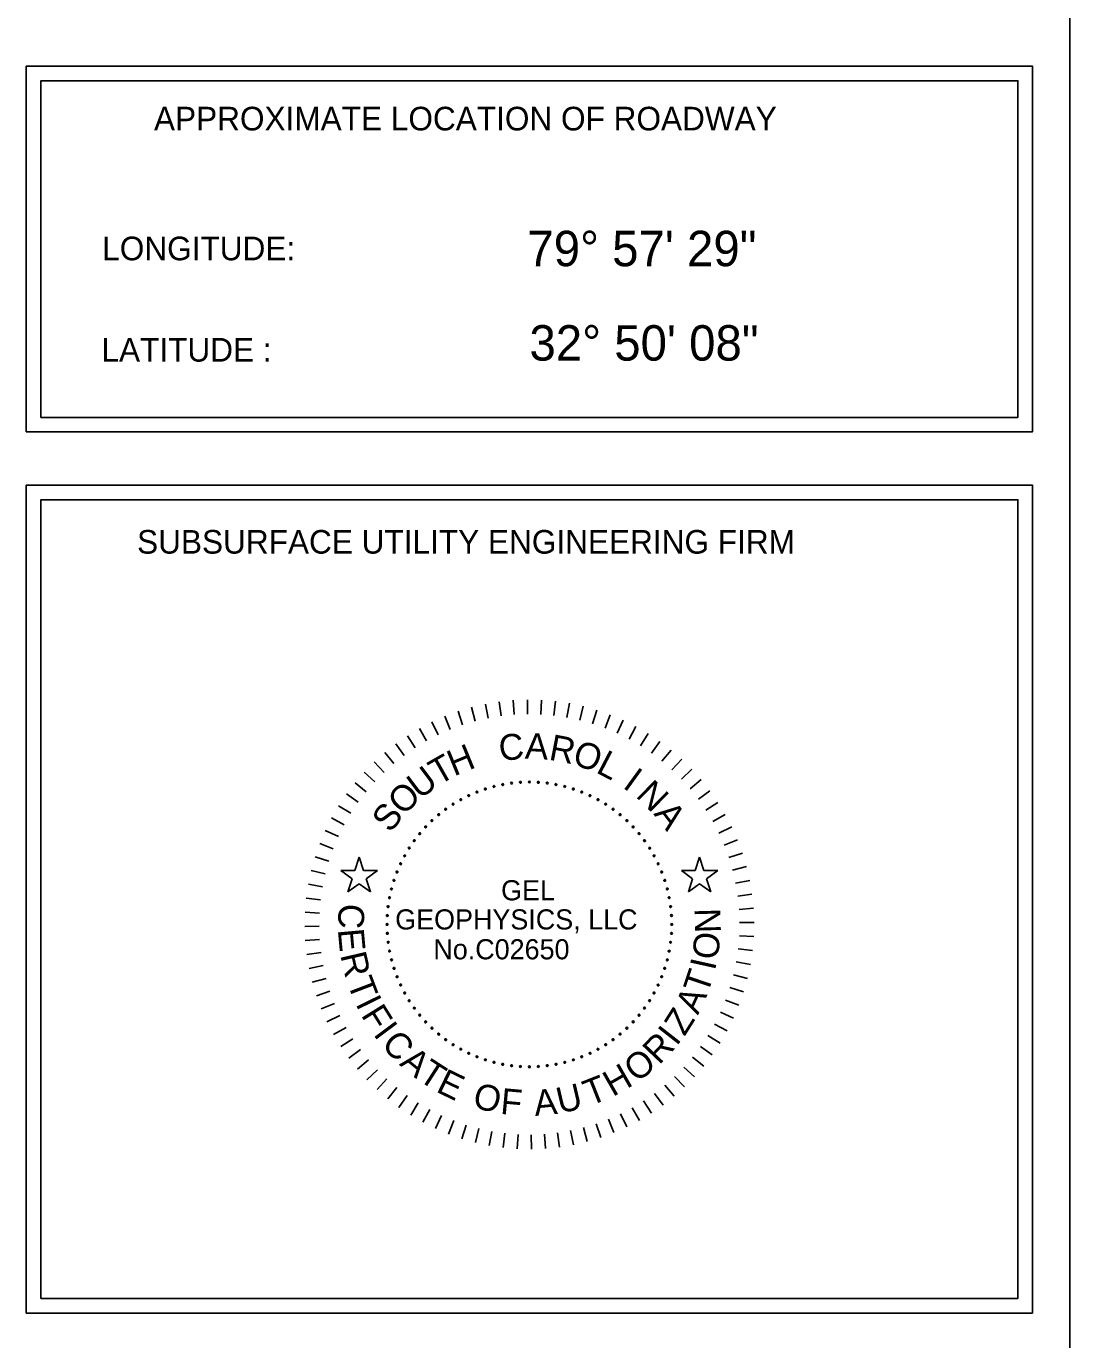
# Model space of a CAD drawing. Extents: x 190073 to 191750, y 195724 to 196797.
# Drawn here: x 191526.6 to 191747.6, y 196008.5 to 196286.5 of the extents above; entities that cross this region are included whole.
import ezdxf

# ---------------------------------------------------------------- set-up
doc = ezdxf.new("R2010")
doc.units = 0
for name, color, linetype in [('RD_EX_SU_H2O', 7, 'Continuous'), ('RD_SHT_Bndy', 7, 'Continuous'), ('RD_SHT_TX', 7, 'Continuous')]:
    doc.layers.add(name, color=color, linetype=linetype)

# ---------------------------------------------------------------- blocks, each defined once
blk = doc.blocks.new('GEGSC')
for p, q in [((-0.6324, 0.1948), (-0.6485, 0.1451)), ((-0.6162, 0.1451), (-0.6324, 0.1948)), ((0.6313, 0.1451), (0.6474, 0.1948)), ((0.6474, 0.1948), (0.6635, 0.1451)), ((-0.6485, 0.1451), (-0.7007, 0.1451)), ((-0.7007, 0.1451), (-0.6585, 0.1144)), ((-0.6585, 0.1144), (-0.6746, 0.0648)), ((-0.564, 0.1451), (-0.6162, 0.1451)), ((-0.6063, 0.1144), (-0.564, 0.1451)), ((-0.5901, 0.0648), (-0.6063, 0.1144)), ((0.5791, 0.1451), (0.6313, 0.1451)), ((0.6213, 0.1144), (0.5791, 0.1451)), ((0.6052, 0.0648), (0.6213, 0.1144)), ((0.6635, 0.1451), (0.7158, 0.1451)), ((0.7158, 0.1451), (0.6735, 0.1144)), ((0.6735, 0.1144), (0.6897, 0.0648)), ((-0.6746, 0.0648), (-0.6324, 0.0955)), ((-0.6324, 0.0955), (-0.5901, 0.0648)), ((0.6474, 0.0955), (0.6052, 0.0648)), ((0.6897, 0.0648), (0.6474, 0.0955))]:
    blk.add_line(p, q)
for points in [[(-0.2605, 0.7434), (-0.2434, 0.6922)], [(-0.2097, 0.7587), (-0.1958, 0.7064)], [(-0.158, 0.7707), (-0.1474, 0.7177)], [(-0.1057, 0.7795), (-0.0985, 0.7259)], [(-0.0529, 0.7849), (-0.0491, 0.731)], [(0.0001, 0.7871), (0.0006, 0.733)], [(0.0531, 0.7859), (0.0502, 0.7319)], [(0.106, 0.7813), (0.0997, 0.7276)], [(0.1585, 0.7735), (0.1488, 0.7203)], [(0.2103, 0.7624), (0.1974, 0.7099)], [(0.2614, 0.748), (0.2452, 0.6965)], [(-0.3588, 0.7035), (-0.3353, 0.6548)], [(-0.3103, 0.725), (-0.2899, 0.6749)], [(0.3115, 0.7305), (0.292, 0.6801)], [(0.3604, 0.7099), (0.3378, 0.6607)], [(-0.4513, 0.6516), (-0.4219, 0.6062)], [(-0.4058, 0.679), (-0.3794, 0.6319)], [(0.4078, 0.6862), (0.3822, 0.6386)], [(0.4537, 0.6596), (0.4252, 0.6137)], [(-0.4949, 0.6214), (-0.4627, 0.5779)], [(0.4979, 0.6301), (0.4665, 0.5861)], [(0.5401, 0.598), (0.506, 0.5561)], [(-0.576, 0.5531), (-0.5387, 0.514)], [(-0.5365, 0.5885), (-0.5017, 0.5472)], [(0.5802, 0.5633), (0.5435, 0.5235)], [(-0.6132, 0.5152), (-0.5735, 0.4786)], [(0.618, 0.5261), (0.579, 0.4887)], [(-0.6479, 0.4751), (-0.606, 0.441)], [(0.6535, 0.4866), (0.6121, 0.4518)], [(0.6864, 0.445), (0.6429, 0.4128)], [(-0.6801, 0.4329), (-0.6361, 0.4015)], [(0.7166, 0.4013), (0.6712, 0.372)], [(-0.7095, 0.3888), (-0.6636, 0.3602)], [(0.744, 0.3559), (0.6969, 0.3295)], [(-0.7361, 0.3429), (-0.6885, 0.3172)], [(0.7685, 0.3089), (0.7198, 0.2854)], [(-0.7598, 0.2954), (-0.7107, 0.2728)], [(0.79, 0.2604), (0.7399, 0.24)], [(-0.7804, 0.2465), (-0.73, 0.2271)], [(0.8084, 0.2106), (0.7571, 0.1934)], [(-0.798, 0.1964), (-0.7464, 0.1802)], [(0.8236, 0.1598), (0.7714, 0.1459)], [(-0.8123, 0.1454), (-0.7598, 0.1324)], [(0.8357, 0.1081), (0.7827, 0.0975)], [(-0.8234, 0.0935), (-0.7702, 0.0838)], [(0.8444, 0.0558), (0.7909, 0.0485)], [(-0.8313, 0.041), (-0.7776, 0.0347)], [(0.8499, 0.003), (0.796, -0.0009)], [(-0.8358, -0.0119), (-0.7818, -0.0148)], [(-0.837, -0.0649), (-0.7829, -0.0644)], [(0.852, -0.05), (0.798, -0.0505)], [(-0.8348, -0.1179), (-0.7809, -0.114)], [(0.8508, -0.103), (0.7969, -0.1001)], [(-0.8294, -0.1707), (-0.7758, -0.1634)], [(0.8463, -0.1559), (0.7926, -0.1496)], [(-0.8206, -0.223), (-0.7676, -0.2124)], [(0.8385, -0.2084), (0.7853, -0.1987)], [(-0.8086, -0.2747), (-0.7564, -0.2608)], [(0.813, -0.3113), (0.7614, -0.2951)], [(0.8274, -0.2603), (0.7749, -0.2473)], [(-0.7933, -0.3255), (-0.7421, -0.3083)], [(0.7955, -0.3614), (0.745, -0.342)], [(-0.7749, -0.3753), (-0.7249, -0.3549)], [(0.7748, -0.4103), (0.7257, -0.3877)], [(-0.7534, -0.4238), (-0.7047, -0.4003)], [(0.7512, -0.4578), (0.7036, -0.4321)], [(-0.7289, -0.4708), (-0.6818, -0.4444)], [(-0.7015, -0.5162), (-0.6561, -0.4869)], [(0.7246, -0.5037), (0.6787, -0.4751)], [(-0.6713, -0.5599), (-0.6279, -0.5277)], [(0.6951, -0.5478), (0.6511, -0.5164)], [(-0.6384, -0.6015), (-0.5971, -0.5667)], [(0.663, -0.59), (0.621, -0.5559)], [(-0.603, -0.641), (-0.5639, -0.6036)], [(-0.5652, -0.6782), (-0.5285, -0.6384)], [(0.5911, -0.668), (0.5537, -0.6289)], [(0.6282, -0.6301), (0.5885, -0.5935)], [(-0.525, -0.7129), (-0.491, -0.671)], [(0.5516, -0.7034), (0.5168, -0.6621)], [(-0.4828, -0.745), (-0.4515, -0.701)], [(-0.4387, -0.7745), (-0.4101, -0.7286)], [(0.4663, -0.7665), (0.437, -0.7211)], [(0.5099, -0.7363), (0.4778, -0.6928)], [(-0.3928, -0.8011), (-0.3672, -0.7535)], [(-0.3453, -0.8248), (-0.3227, -0.7756)], [(0.3738, -0.8184), (0.3504, -0.7697)], [(0.4209, -0.7939), (0.3944, -0.7468)], [(-0.2964, -0.8454), (-0.277, -0.795)], [(-0.2464, -0.8629), (-0.2301, -0.8114)], [(-0.1953, -0.8773), (-0.1823, -0.8248)], [(-0.1434, -0.8884), (-0.1337, -0.8352)], [(0.1731, -0.8856), (0.1625, -0.8326)], [(0.2248, -0.8736), (0.2109, -0.8213)], [(0.2756, -0.8583), (0.2584, -0.8071)], [(0.3253, -0.8399), (0.305, -0.7898)], [(-0.0909, -0.8962), (-0.0846, -0.8426)], [(-0.0381, -0.9008), (-0.0352, -0.8468)], [(0.015, -0.902), (0.0145, -0.8479)], [(0.068, -0.8998), (0.0641, -0.8459)], [(0.1208, -0.8944), (0.1135, -0.8408)]]:
    blk.add_lwpolyline(points)
for centre, start, end in [((-0.1578, 0.4515), 108, 288), ((-0.1578, 0.4515), 288, 108), ((-0.1256, 0.4608), 104.4, 284.4), ((-0.1256, 0.4608), 284.4, 104.4), ((-0.0927, 0.4682), 100.8, 280.8), ((-0.0927, 0.4682), 280.8, 100.8), ((-0.0595, 0.4734), 97.2, 277.2), ((-0.0595, 0.4734), 277.2, 97.2), ((-0.0261, 0.4766), 93.6, 273.6), ((-0.0261, 0.4766), 273.6, 93.6), ((0.0075, 0.4777), 90, 270), ((0.0075, 0.4777), 270, 90), ((0.0411, 0.4766), 86.4, 266.4), ((0.0411, 0.4766), 266.4, 86.4), ((0.0746, 0.4734), 82.8, 262.8), ((0.0746, 0.4734), 262.8, 82.8), ((0.1078, 0.4682), 79.2, 259.2), ((0.1078, 0.4682), 259.2, 79.2), ((0.1406, 0.4608), 75.6, 255.6), ((0.1406, 0.4608), 255.6, 75.6), ((0.1729, 0.4515), 72, 252), ((0.1729, 0.4515), 252, 72), ((-0.2792, 0.3944), 122.4, 302.4), ((-0.2792, 0.3944), 302.4, 122.4), ((-0.2503, 0.4115), 118.8, 298.8), ((-0.2503, 0.4115), 298.8, 118.8), ((-0.2203, 0.4267), 115.2, 295.2), ((-0.2203, 0.4267), 295.2, 115.2), ((-0.1895, 0.4401), 111.6, 291.6), ((-0.1895, 0.4401), 291.6, 111.6), ((0.2045, 0.4401), 68.4, 248.4), ((0.2045, 0.4401), 248.4, 68.4), ((0.2354, 0.4267), 64.8, 244.8), ((0.2354, 0.4267), 244.8, 64.8), ((0.2653, 0.4115), 61.2, 241.2), ((0.2653, 0.4115), 241.2, 61.2), ((0.2942, 0.3944), 57.6, 237.6), ((0.2942, 0.3944), 237.6, 57.6), ((-0.3336, 0.3549), 129.6, 309.6), ((-0.3336, 0.3549), 309.6, 129.6), ((-0.307, 0.3755), 126, 306), ((-0.307, 0.3755), 306, 126), ((0.322, 0.3755), 54, 234), ((0.322, 0.3755), 234, 54), ((0.3486, 0.3549), 50.4, 230.4), ((0.3486, 0.3549), 230.4, 50.4), ((-0.3825, 0.3089), 136.8, 316.8), ((-0.3825, 0.3089), 316.8, 136.8), ((-0.3588, 0.3326), 133.2, 313.2), ((-0.3588, 0.3326), 313.2, 133.2), ((0.3738, 0.3326), 46.8, 226.8), ((0.3738, 0.3326), 226.8, 46.8), ((0.3976, 0.3089), 43.2, 223.2), ((0.3976, 0.3089), 223.2, 43.2), ((-0.4254, 0.2571), 144, 324), ((-0.4254, 0.2571), 324, 144), ((-0.4048, 0.2836), 140.4, 320.4), ((-0.4048, 0.2836), 320.4, 140.4), ((0.4198, 0.2836), 39.6, 219.6), ((0.4198, 0.2836), 219.6, 39.6), ((0.4404, 0.2571), 36, 216), ((0.4404, 0.2571), 216, 36), ((-0.4614, 0.2003), 151.2, 331.2), ((-0.4614, 0.2003), 331.2, 151.2), ((-0.4443, 0.2293), 147.6, 327.6), ((-0.4443, 0.2293), 327.6, 147.6), ((0.4593, 0.2293), 32.4, 212.4), ((0.4593, 0.2293), 212.4, 32.4), ((0.4764, 0.2003), 28.8, 208.8), ((0.4764, 0.2003), 208.8, 28.8), ((-0.4767, 0.1704), 154.8, 334.8), ((-0.4767, 0.1704), 334.8, 154.8), ((0.4917, 0.1704), 25.2, 205.2), ((0.4917, 0.1704), 205.2, 25.2), ((-0.5014, 0.1079), 162, 342), ((-0.5014, 0.1079), 342, 162), ((-0.49, 0.1395), 158.4, 338.4), ((-0.49, 0.1395), 338.4, 158.4), ((0.505, 0.1395), 21.6, 201.6), ((0.505, 0.1395), 201.6, 21.6), ((0.5164, 0.1079), 18, 198), ((0.5164, 0.1079), 198, 18), ((-0.5108, 0.0756), 165.6, 345.6), ((-0.5108, 0.0756), 345.6, 165.6), ((0.5258, 0.0756), 14.4, 194.4), ((0.5258, 0.0756), 194.4, 14.4), ((-0.5234, 0.0096), 352.8, 172.8), ((-0.5234, 0.0096), 172.8, 352.8), ((-0.5181, 0.0428), 169.2, 349.2), ((-0.5181, 0.0428), 349.2, 169.2), ((0.5331, 0.0428), 10.8, 190.8), ((0.5331, 0.0428), 190.8, 10.8), ((0.5384, 0.0096), 7.2, 187.2), ((0.5384, 0.0096), 187.2, 7.2), ((-0.5265, -0.0239), 356.4, 176.4), ((-0.5265, -0.0239), 176.4, 356.4), ((0.5416, -0.0239), 3.6, 183.6), ((0.5416, -0.0239), 183.6, 3.6), ((-0.5276, -0.0575), 0, 180), ((-0.5276, -0.0575), 180, 0), ((-0.5265, -0.091), 3.6, 183.6), ((-0.5265, -0.091), 183.6, 3.6), ((0.5416, -0.091), 356.4, 176.4), ((0.5416, -0.091), 176.4, 356.4), ((0.5426, -0.0575), 0, 180), ((0.5426, -0.0575), 180, 0), ((-0.5234, -0.1245), 7.2, 187.2), ((-0.5234, -0.1245), 187.2, 7.2), ((0.5384, -0.1245), 172.8, 352.8), ((0.5384, -0.1245), 352.8, 172.8), ((-0.5181, -0.1577), 10.8, 190.8), ((-0.5181, -0.1577), 190.8, 10.8), ((-0.5108, -0.1905), 14.4, 194.4), ((-0.5108, -0.1905), 194.4, 14.4), ((0.5258, -0.1905), 165.6, 345.6), ((0.5258, -0.1905), 345.6, 165.6), ((0.5331, -0.1577), 349.2, 169.2), ((0.5331, -0.1577), 169.2, 349.2), ((-0.5014, -0.2228), 18, 198), ((-0.5014, -0.2228), 198, 18), ((0.5164, -0.2228), 162, 342), ((0.5164, -0.2228), 342, 162), ((-0.49, -0.2544), 21.6, 201.6), ((-0.49, -0.2544), 201.6, 21.6), ((-0.4767, -0.2853), 25.2, 205.2), ((-0.4767, -0.2853), 205.2, 25.2), ((0.4917, -0.2853), 154.8, 334.8), ((0.4917, -0.2853), 334.8, 154.8), ((0.505, -0.2544), 158.4, 338.4), ((0.505, -0.2544), 338.4, 158.4), ((-0.4614, -0.3152), 28.8, 208.8), ((-0.4614, -0.3152), 208.8, 28.8), ((-0.4443, -0.3442), 32.4, 212.4), ((-0.4443, -0.3442), 212.4, 32.4), ((0.4593, -0.3442), 147.6, 327.6), ((0.4593, -0.3442), 327.6, 147.6), ((0.4764, -0.3152), 151.2, 331.2), ((0.4764, -0.3152), 331.2, 151.2), ((-0.4254, -0.372), 36, 216), ((-0.4254, -0.372), 216, 36), ((0.4404, -0.372), 144, 324), ((0.4404, -0.372), 324, 144), ((-0.4048, -0.3985), 39.6, 219.6), ((-0.4048, -0.3985), 219.6, 39.6), ((-0.3825, -0.4238), 43.2, 223.2), ((-0.3825, -0.4238), 223.2, 43.2), ((-0.3588, -0.4475), 46.8, 226.8), ((0.3738, -0.4475), 313.2, 133.2), ((0.3976, -0.4238), 136.8, 316.8), ((0.3976, -0.4238), 316.8, 136.8), ((0.4198, -0.3985), 140.4, 320.4), ((0.4198, -0.3985), 320.4, 140.4), ((-0.3588, -0.4475), 226.8, 46.8), ((-0.3336, -0.4698), 50.4, 230.4), ((-0.3336, -0.4698), 230.4, 50.4), ((-0.307, -0.4904), 54, 234), ((-0.307, -0.4904), 234, 54), ((0.322, -0.4904), 126, 306), ((0.322, -0.4904), 306, 126), ((0.3486, -0.4698), 129.6, 309.6), ((0.3486, -0.4698), 309.6, 129.6), ((0.3738, -0.4475), 133.2, 313.2), ((-0.2792, -0.5093), 57.6, 237.6), ((-0.2792, -0.5093), 237.6, 57.6), ((-0.2503, -0.5264), 61.2, 241.2), ((-0.2503, -0.5264), 241.2, 61.2), ((-0.2203, -0.5416), 64.8, 244.8), ((-0.2203, -0.5416), 244.8, 64.8), ((0.2354, -0.5416), 115.2, 295.2), ((0.2354, -0.5416), 295.2, 115.2), ((0.2653, -0.5264), 118.8, 298.8), ((0.2653, -0.5264), 298.8, 118.8), ((0.2942, -0.5093), 122.4, 302.4), ((0.2942, -0.5093), 302.4, 122.4), ((-0.1895, -0.555), 68.4, 248.4), ((-0.1895, -0.555), 248.4, 68.4), ((-0.1578, -0.5664), 72, 252), ((-0.1578, -0.5664), 252, 72), ((-0.1256, -0.5757), 75.6, 255.6), ((-0.1256, -0.5757), 255.6, 75.6), ((-0.0927, -0.5831), 79.2, 259.2), ((-0.0927, -0.5831), 259.2, 79.2), ((-0.0595, -0.5883), 82.8, 262.8), ((-0.0595, -0.5883), 262.8, 82.8), ((-0.0261, -0.5915), 86.4, 266.4), ((-0.0261, -0.5915), 266.4, 86.4), ((0.0075, -0.5926), 90, 270), ((0.0075, -0.5926), 270, 90), ((0.0411, -0.5915), 93.6, 273.6), ((0.0411, -0.5915), 273.6, 93.6), ((0.0746, -0.5883), 97.2, 277.2), ((0.0746, -0.5883), 277.2, 97.2), ((0.1078, -0.5831), 100.8, 280.8), ((0.1078, -0.5831), 280.8, 100.8), ((0.1406, -0.5757), 104.4, 284.4), ((0.1406, -0.5757), 284.4, 104.4), ((0.1729, -0.5664), 108, 288), ((0.1729, -0.5664), 288, 108), ((0.2045, -0.555), 111.6, 291.6), ((0.2045, -0.555), 291.6, 111.6)]:
    blk.add_arc(centre, 0.00338, start, end)
for s, rotation, p in [('C', 5.7029, (-0.1027, 0.5564)), ('A', 357.3878, (-0.0104, 0.5658)), ('R', 349.0726, (0.0776, 0.5622)), ('H', 22.3333, (-0.2759, 0.4983)), ('O', 340.7575, (0.1643, 0.5464)), ('L', 332.4423, (0.2541, 0.5152)), ('T', 29.6546, (-0.3343, 0.4634)), ('U', 36.7547, (-0.4054, 0.4102)), ('I', 324.1272, (0.355, 0.4586)), ('O', 44.7303, (-0.4662, 0.3484)), ('N', 315.812, (0.4043, 0.4239)), ('S', 52.6202, (-0.5147, 0.2832)), ('A', 307.4969, (0.4726, 0.3578)), ('C', 267.5615, (-0.7088, 0.0217)), ('N', 91.5592, (0.7277, -0.0888)), ('E', 275.2306, (-0.7127, -0.0769)), ('O', 83.2441, (0.7156, -0.1926)), ('R', 283.0282, (-0.704, -0.1721)), ('I', 77.4808, (0.7049, -0.2337)), ('T', 290.835, (-0.6785, -0.2764)), ('T', 71.4182, (0.6765, -0.3239)), ('I', 296.0972, (-0.6474, -0.355)), ('A', 65.2613, (0.6412, -0.4004)), ('F', 301.9012, (-0.6274, -0.3981)), ('Z', 57.739, (0.5908, -0.4804)), ('I', 306.6661, (-0.5817, -0.4701)), ('I', 51.916, (0.5606, -0.5174)), ('C', 312.8388, (-0.5528, -0.5107)), ('R', 46.453, (0.4952, -0.5881)), ('A', 320.687, (-0.4839, -0.5844)), ('O', 38.1378, (0.4115, -0.6545)), ('T', 327.1751, (-0.4153, -0.6403)), ('H', 29.8227, (0.3209, -0.7066)), ('E', 334.1811, (-0.3473, -0.6845)), ('T', 21.5075, (0.2345, -0.7409)), ('O', 346.4959, (-0.2099, -0.7447)), ('F', 354.8111, (-0.1036, -0.7693)), ('A', 5.4043, (0.0291, -0.7776)), ('U', 13.1924, (0.122, -0.7691))]:
    blk.add_text(s, height=0.0973, rotation=rotation).set_placement(p)
for s, height, p in [('GEL', 0.07567, (-0.0988, 0.033)), ('GEOPHYSICS, LLC', 0.075671, (-0.4969, -0.0765)), (' No.C02650', 0.07567, (-0.3816, -0.1887))]:
    blk.add_text(s, height=height).set_placement(p)

msp = doc.modelspace()

# ---------------------------------------------------------------- linework, layer by layer
at = {"layer": 'RD_SHT_Bndy'}
msp.add_line((191747.56, 195747.12), (191747.56, 196797.12), dxfattribs=at)
for points in [[(191526.6, 196200.62), (191739.67, 196200.62), (191739.67, 196278.05), (191526.6, 196278.05)], [(191529.69, 196203.71), (191736.58, 196203.71), (191736.58, 196274.95), (191529.69, 196274.95)], [(191526.6, 196014.09), (191739.67, 196014.09), (191739.67, 196189.36), (191526.6, 196189.36)], [(191529.69, 196017.19), (191736.58, 196017.19), (191736.58, 196186.26), (191529.69, 196186.26)]]:
    msp.add_lwpolyline(points, close=True, dxfattribs=at)

# ---------------------------------------------------------------- block references
at = {"layer": 'RD_EX_SU_H2O', "xscale": 56.32556603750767, "yscale": 56.32556603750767}
msp.add_blockref('GEGSC', (191632.71, 196099.61), dxfattribs=at)

# ---------------------------------------------------------------- texts
at = {"layer": 'RD_SHT_TX'}
for s, height, p in [('APPROXIMATE LOCATION OF ROADWAY', 5, (191553.64, 196264.45)), ('LONGITUDE: ', 5, (191542.68, 196236.96)), ('79%%d 57\' 29"', 7.5, (191632.71, 196235.7)), ('32%%d 50\' 08"', 7.5, (191633.15, 196215.72)), ('LATITUDE : ', 5, (191542.52, 196215.51)), ('SUBSURFACE UTILITY ENGINEERING FIRM', 5, (191550.06, 196174.86))]:
    msp.add_text(s, height=height, dxfattribs=at).set_placement(p)

doc.saveas('drawing.dxf')
